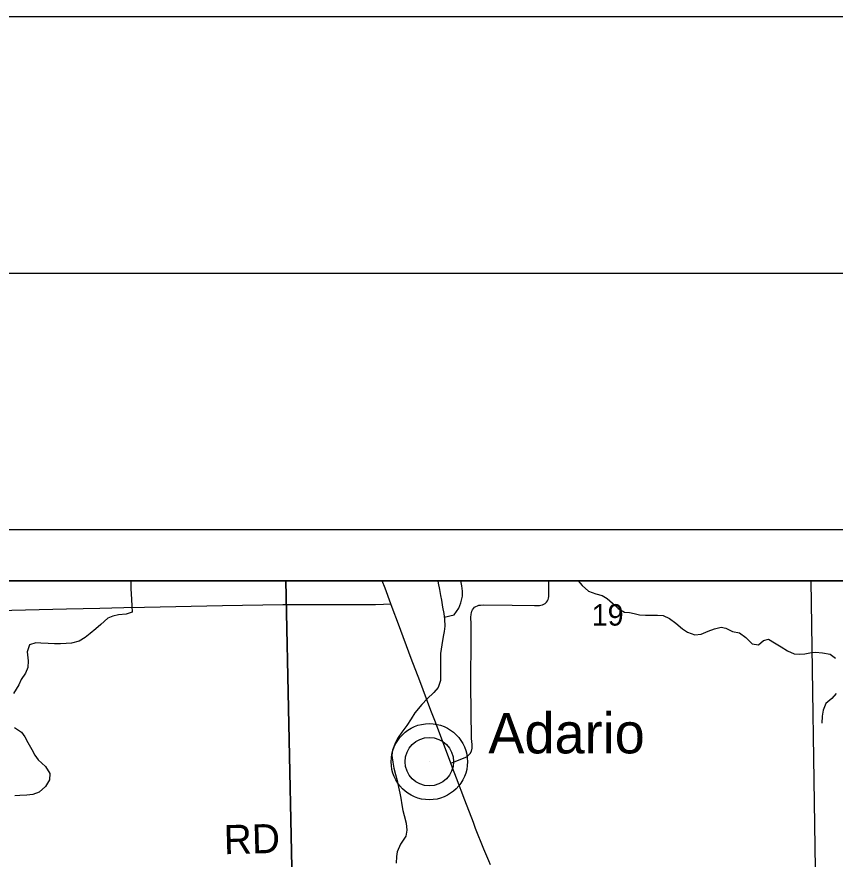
# Model space of a CAD drawing. Extents: x 0 to 70.2, y 0 to 31.4.
# Drawn here: x 4.18 to 5.776, y 20.357 to 22 of the extents above; entities that cross this region are included whole.
import ezdxf

# ---------------------------------------------------------------- set-up
doc = ezdxf.new("R2010")
doc.units = 0
for name, color, linetype in [('GM_X_County_Road', 7, 'Continuous'), ('GM_X_County_Road_Text', 7, 'Continuous'), ('GM_X_Minor_River', 7, 'Continuous'), ('GM_X_Section_Text', 7, 'Continuous'), ('GM_X_State_Route', 7, 'Continuous'), ('GM_X_Township_Road', 7, 'Continuous'), ('GM_X_Unincorporated', 7, 'Continuous'), ('GM_X_Unincorporated_Location', 7, 'Continuous'), ('GM_X_Unincorporated_Text', 7, 'Continuous'), ('SH_Border', 7, 'Continuous'), ('SH_Cut_Line', 7, 'Continuous'), ('SH_Data', 7, 'Continuous')]:
    doc.layers.add(name, color=color, linetype=linetype)

msp = doc.modelspace()

# ---------------------------------------------------------------- linework, layer by layer
at = {"layer": 'GM_X_County_Road'}
for points in [[(4.9094, 20.8549), (4.898, 20.8852), (4.8923, 20.9)], [(5.0262, 20.5443), (4.9962, 20.6237), (4.9874, 20.6466), (4.9658, 20.7049), (4.9491, 20.7484), (4.9245, 20.8154), (4.9122, 20.8474), (4.9094, 20.8549)], [(5.1036, 20.3455), (5.1003, 20.3533), (5.0907, 20.3762), (5.0746, 20.4168), (5.0732, 20.4206), (5.0703, 20.4283), (5.054, 20.4719), (5.0374, 20.5145), (5.0298, 20.5347), (5.0262, 20.5443)]]:
    msp.add_lwpolyline(points, dxfattribs=at)
at = {"layer": 'GM_X_Minor_River'}
for points in [[(4.4019, 20.9), (4.402, 20.8944), (4.402, 20.8849), (4.4027, 20.8739), (4.403, 20.8637), (4.4041, 20.85), (4.4044, 20.8386), (4.393, 20.8345), (4.3778, 20.8331), (4.3672, 20.8305), (4.3569, 20.8267), (4.3432, 20.8146), (4.3337, 20.8059), (4.3227, 20.7969), (4.3131, 20.7894), (4.301, 20.7818), (4.2861, 20.7781), (4.2759, 20.7778), (4.2645, 20.7771), (4.2531, 20.7771), (4.241, 20.7776), (4.2262, 20.7784), (4.2167, 20.7788), (4.2042, 20.7751), (4.1999, 20.7614), (4.2014, 20.7436), (4.2009, 20.7307), (4.1967, 20.7193), (4.1883, 20.7072), (4.1833, 20.6966), (4.1733, 20.68)], [(5.0011, 20.9), (5.0019, 20.8949), (5.0042, 20.8828), (5.006, 20.8714), (5.0079, 20.8619)], [(5.0136, 20.829), (5.0328, 20.8337), (5.0419, 20.8461), (5.0458, 20.8567), (5.0493, 20.8696), (5.0493, 20.8795), (5.0478, 20.8898), (5.046, 20.8996), (5.0459, 20.9)], [(5.2748, 20.9), (5.2827, 20.8905), (5.2948, 20.8798), (5.3092, 20.8741), (5.3217, 20.8713), (5.3315, 20.8656), (5.3421, 20.8564), (5.3527, 20.8458), (5.3652, 20.8385), (5.3747, 20.8377), (5.3841, 20.8361), (5.3948, 20.8334), (5.4065, 20.8326), (5.4168, 20.8325), (5.4297, 20.8329), (5.4407, 20.8321), (5.4528, 20.8263), (5.4656, 20.8171), (5.4781, 20.8064), (5.4879, 20.7996), (5.5023, 20.7946), (5.5149, 20.796), (5.5285, 20.8013), (5.5407, 20.8061), (5.5536, 20.8095), (5.5631, 20.8072), (5.576, 20.801), (5.5896, 20.7983), (5.6021, 20.7895), (5.6142, 20.7769), (5.6267, 20.7746), (5.6362, 20.7833), (5.6465, 20.7859), (5.6578, 20.7786), (5.6707, 20.771), (5.6832, 20.7629), (5.696, 20.7572), (5.7063, 20.7564), (5.7169, 20.7575), (5.7268, 20.7593), (5.7382, 20.7608), (5.7518, 20.7596), (5.7666, 20.7565), (5.7772, 20.7488)], [(5.0079, 20.8619), (5.0101, 20.8482), (5.0127, 20.8357), (5.0141, 20.825), (5.0144, 20.811), (5.0133, 20.8007), (5.0113, 20.7909), (5.009, 20.775), (5.0062, 20.7583), (5.0062, 20.7457), (5.0065, 20.7328), (5.0064, 20.7199), (5.006, 20.7051), (5.0017, 20.6919), (4.9933, 20.6821), (4.9804, 20.6696), (4.9697, 20.6586), (4.9559, 20.642), (4.9487, 20.6307), (4.9403, 20.6178), (4.9307, 20.6042), (4.9235, 20.594), (4.9185, 20.5841), (4.9123, 20.5694), (4.9115, 20.5591), (4.913, 20.5462), (4.9152, 20.5344), (4.9186, 20.5219), (4.9219, 20.5101), (4.9245, 20.4972), (4.9271, 20.4858), (4.9286, 20.4759), (4.9308, 20.4626), (4.933, 20.452), (4.9356, 20.4417), (4.939, 20.4273), (4.9404, 20.4136), (4.9385, 20.4019), (4.9281, 20.386), (4.9216, 20.3712), (4.9201, 20.3617), (4.9196, 20.3492)], [(5.778, 20.6801), (5.77, 20.6703), (5.7582, 20.6605), (5.7528, 20.6476), (5.7509, 20.6355), (5.75, 20.6222)], [(4.1753, 20.6136), (4.1885, 20.6048), (4.1949, 20.5952), (4.201, 20.5846), (4.2089, 20.5705), (4.2149, 20.5599), (4.2213, 20.5503), (4.2353, 20.5374), (4.2439, 20.524), (4.2431, 20.5115), (4.2355, 20.4983), (4.2233, 20.4873), (4.2111, 20.4828), (4.1989, 20.4818), (4.1857, 20.4811), (4.1758, 20.4804)]]:
    msp.add_lwpolyline(points, dxfattribs=at)
at = {"layer": 'GM_X_Section_Text'}
msp.add_lwpolyline([(6.7343, 20.9), (2.6577, 20.9)], dxfattribs=at)
at = {"layer": 'GM_X_State_Route'}
for points in [[(4.7047, 20.9), (3.6817, 20.9), (3.6935, 20.3278), (4.716, 20.3402)], [(5.7295, 20.9), (4.7047, 20.9), (4.716, 20.3402), (5.7381, 20.3376)]]:
    msp.add_lwpolyline(points, close=True, dxfattribs=at)
at = {"layer": 'GM_X_Township_Road'}
for points in [[(5.0262, 20.5443), (5.0328, 20.5469), (5.0545, 20.5552), (5.0584, 20.5572), (5.0638, 20.5629), (5.067, 20.5677), (5.0681, 20.573), (5.0681, 20.5803), (5.0669, 20.5919), (5.0651, 20.697), (5.0652, 20.7281), (5.0653, 20.7321), (5.0663, 20.7567), (5.0658, 20.8159), (5.0657, 20.8282), (5.0661, 20.8344), (5.0667, 20.8375), (5.0676, 20.8404), (5.0689, 20.8433), (5.0706, 20.8459), (5.0728, 20.8481), (5.0753, 20.8499), (5.0781, 20.8512), (5.0811, 20.852), (5.0842, 20.8525), (5.0904, 20.8529), (5.1463, 20.8524), (5.1898, 20.8516), (5.1991, 20.8519), (5.2022, 20.8522), (5.2052, 20.8529), (5.2081, 20.8541), (5.2107, 20.8558), (5.2129, 20.8579), (5.2147, 20.8605), (5.216, 20.8633), (5.2169, 20.8662), (5.2175, 20.8693), (5.2179, 20.8755), (5.2178, 20.9)], [(3.9051, 20.8371), (3.9222, 20.8374), (4.0651, 20.8404), (4.1428, 20.842), (4.2764, 20.8449), (4.3416, 20.8464), (4.3882, 20.8474), (4.4286, 20.8484), (4.5808, 20.8519), (4.6989, 20.8537), (4.7734, 20.8536), (4.8449, 20.8534), (4.8791, 20.8536), (4.8947, 20.8542), (4.9094, 20.8549)]]:
    msp.add_lwpolyline(points, dxfattribs=at)
at = {"layer": 'GM_X_Unincorporated'}
for radius in [0.0744, 0.0472]:
    msp.add_circle((4.9844, 20.5469), radius, dxfattribs=at)
at = {"layer": 'GM_X_Unincorporated_Location'}
msp.add_line((4.9844, 20.5469), (4.9844, 20.5469), dxfattribs=at)
at = {"layer": 'SH_Border'}
msp.add_lwpolyline([(1.5, 21.5), (33.5, 21.5), (33.5, 0.5), (1.5, 0.5)], close=True, dxfattribs=at)
at = {"layer": 'SH_Cut_Line'}
msp.add_lwpolyline([(0, 0), (34, 0), (34, 22), (0, 22)], close=True, dxfattribs=at)
msp.add_lwpolyline([(6.7786, 18.1369), (6.7742, 18.3058), (6.7461, 18.306), (6.749, 19.3206), (6.7395, 20.3365), (6.7343, 20.9), (2.1, 20.9), (2.1, 14.1)], dxfattribs=at)
at = {"layer": 'SH_Data'}
for p, q in [((2, 21), (9, 21)), ((2.1, 20.9), (8.9, 20.9))]:
    msp.add_line(p, q, dxfattribs=at)

# ---------------------------------------------------------------- texts
at = {"layer": 'GM_X_County_Road_Text'}
msp.add_text('RD', height=0.05682, rotation=1.4808, dxfattribs=at).set_placement((4.584, 20.3663))
at = {"layer": 'GM_X_Section_Text'}
msp.add_text('19', height=0.04186, rotation=0, dxfattribs=at).set_placement((5.3012, 20.8124))
at = {"layer": 'GM_X_Unincorporated_Text'}
msp.add_text('Adario', height=0.07898, rotation=0, dxfattribs=at).set_placement((5.0995, 20.5631))

doc.saveas('drawing.dxf')
